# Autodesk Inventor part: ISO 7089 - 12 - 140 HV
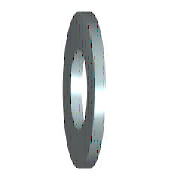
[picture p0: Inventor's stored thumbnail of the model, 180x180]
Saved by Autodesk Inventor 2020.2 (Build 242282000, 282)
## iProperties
Manager: www.cadconsulting.pl
Company: Fabian Stasiak CAD Consulting
Created: 2010-02
Part Number: ISO 7089 - 12 - 140 HV
Material: Spawana stal nierdzewna
Description: Podkładki okrągłe - Szereg normalny - Klasa dokładności A
Document SubType Name: Modeling
Standard: ISO 7089
Designer: F.Stasiak
Standard Revision: Second edition 2000-06-01
Standards Organization: ISO
Language: pl-PL
Size Designation: 12 - 140 HV
Categories: <MemberInstance><Categories><Category DisplayName="Mocowania" InternalName="e4da775c-781d-43d5-af7c-5136215cf5a6" Mnemonic="FSTN"><Category DisplayName="Podkład
Density: 8.08 g/cm^3
Appearance: Metal-Stal
IsCustomPart: 0
Author: F.Stasiak
Subject: Zbiór ćwiczeń. Autodesk Inventor 2020. Kurs podstawowy
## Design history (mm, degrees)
sketch "Sketch"
  geometry: C1 r 12 at (0, 0); C2 r 6.5 at (0, 0); 1 further point
  constraints: 2 centre point, 2 coincident
  dimensions: "d0" = 13 diameter of C2 (= SD1); "d1" = 24 diameter of C1 (= SD2)
extrude "Body" new body sketch "Sketch" distance "d2" = 2.5 (= SD); taper "d3" = 0 deg
workaxis "Work Axis1"
workplane "Work Plane1"
body "Solid1"
other parameters: "SD1" = 13 [user parameter; used in 1 equation term], "SD2" = 24 [user parameter; used in 1 equation term], "SD" = 2.5 [user parameter; used in 1 equation term], "d4" = 0, "d5" = 0, "d6" = 0, "d7" = 0, "NND" = 12 [user parameter]
